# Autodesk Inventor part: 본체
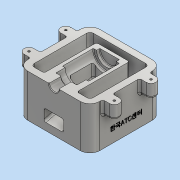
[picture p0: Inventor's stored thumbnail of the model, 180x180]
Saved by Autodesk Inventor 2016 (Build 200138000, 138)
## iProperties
Created: 2018-01
Part Number: 본체
Material: 알루미늄 6061
Document SubType Name: Modeling
Designer: Administrator
Density: 2.7 g/cm^3
Appearance: 알루미늄 - 평지
Mass: 995.217 g
Surface Area: 834.406 cm^2
Volume: 368.599 cm^3
Author: Administrator
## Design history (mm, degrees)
sketch "스케치1"
  geometry: L1 (-55, 55)-(55, 55); L2 (55, 55)-(55, -55); L3 (55, -55)-(-55, -55); L4 (-55, -55)-(-55, 55); L5 (-55, 55)-(55, -55); L6 (55, 55)-(-55, -55); 1 further point
  constraints: 12 end point, 2 midpoint, 2 parallel, 1 horizontal, 1 perpendicular
  dimensions: "d0" = 110 distance of L1.start L1.end; "d1" = 110 distance of L1.end L2.end
extrude "돌출1" new body sketch "스케치1" distance "d2" = 65; taper "d3" = 0 deg
feature "쉘1" dims "d4" = 10
sketch "스케치2"
  geometry: L1 (-45, 0)-(-45, 65) reference; L2 (-45, 8.564)-(35, 30); L3 (35, 30)-(35, 65); L4 (-45, 65)-(45, 65) reference; L5 (35, 65)-(-45, 65); L6 (-45, 65)-(-45, 8.564); L7 (45, 0)-(-45, 0) reference; L8 (55, 0)-(55, 65) reference; 1 further point
  constraints: 8 end point, 1 collinear, 1 parallel, 1 perpendicular, 1 point on line
  dimensions: "d5" = 30 distance from line of L7 L2.end; "d6" = 105 deg angle of L2 L1; "d7" = 20 distance between parallel lines of L8 L3
extrude "돌출2" join sketch "스케치2" stored distance "d8" = 50; taper "d9" = 0 deg
sketch "스케치3"
  geometry: L1 (-55, -55)-(55, -55) reference; L2 (0, -55)-(0, 30); L3 (0, 30)-(-15, 30); L4 (-15, 30)-(-15, 25); L5 (-15, 25)-(-20, 25); L6 (-20, 25)-(-20, -22); L7 (-20, -22)-(-16, -22); L8 (-16, -22)-(-16, -36); L9 (-16, -36)-(-7.5, -36); L10 (-7.5, -36)-(-7.5, -55); L11 (0, -55)-(-7.5, -55); 1 further point
  constraints: 20 end point, 9 perpendicular, 1 midpoint, 1 point on line, 1 vertical
  dimensions: "d10" = 30 diameter of L3.end L2; "d11" = 15 diameter of L10 L2; "d12" = 19 distance of L9.end L10.end; "d13" = 14 distance of L7.end L8.end; "d14" = 47 distance of L5.end L6.end; "d15" = 5 distance of L3.end L4.end; "d16" = 40 diameter of L6 L2; "d17" = 32 diameter of L8 L2
revolve "회전1" sketch "스케치3" stored, may be unused: angle "d18" = 90 deg
sketch "스케치5"
  geometry: L1 (-55, 0)-(-55, 65) reference; L2 (-55, 11.061)-(20, 31.157); L3 (20, 31.157)-(20, 65); L4 (-55, 29.061)-(-17, 39.243); L5 (-17, 39.243)-(-17, 65); L6 (35, 30)-(-45, 8.564) reference; L7 (-45, 65)-(35, 65) reference; L8 (25, 65)-(25, 50) reference; 1 further point
  constraints: 8 end point, 4 point on line, 3 parallel, 1 vertical
  dimensions: "d19" = 5 distance between parallel lines of L6 L2; "d20" = 18 distance of L2.start L4.start; "d21" = 37 distance between parallel lines of L3 L5; "d25" = 5 distance from line of L8 L3.end
extrude "돌출3" cut sketch "스케치5" stored distance "d23" = 30; taper "d24" = 0 deg
sketch "스케치6"
  geometry: L1 (-55, 55)-(-55, -55) reference; L2 (-55, -55)-(-7.5, -55) reference; L3 (-55, -35.5)-(-65, -35.5); L4 (-65, -35.5)-(-65, -20.5); L5 (-65, -20.5)-(-55, -20.5); L6 (-55, -20.5)-(-55, -35.5); A1 r 7.5 centre (-65, -28) between (-65, -20.5) and (-65, -35.5); 1 further point
  constraints: 8 end point, 2 parallel, 2 point on circle, 1 centre point, 1 horizontal, 1 midpoint, 1 perpendicular, 1 point on line
  dimensions: "d26" = 27 distance from line of L2 A1.centre; "d27" = 10 distance of L5.end L4.end; "d28" = 7.5 radius of A1
extrude "돌출4" join sketch "스케치6" distance "d29" = 20; taper "d30" = 0 deg
hole "구멍1" diameter "d33" = 3.242; stored, may be unused: countersink angle "d37" = 90 deg, drill point angle "d39" = 118 deg; dims "d31" = 10, "d32" = 10, "d34" = 9, "d35" = 4, "d36" = 2, "d38" = 11
fillet "모깎기1" dims "d43" = 5
fillet "모깎기2" dims "d44" = 15
sketch "스케치7"
  geometry: L1 (65, 75.5)-(65, 60.5) reference; L2 (0, -34.5)-(65, -34.5) reference; 2 further points
  constraints: 1 other
  dimensions: "d45" = 20 distance from line of L1 point (45, 20.5); "d46" = 55 distance from line of L2 point (45, 20.5)
feature "엠보싱1" sketch "스케치7" dims "d0" = 110, "d1" = 110, "d47" = 0.5, "d48" = 0
fillet "모깎기4" dims "d53" = 3
fillet "모깎기5" dims "d54" = 3
fillet "모깎기6" dims "d55" = 3
fillet "모깎기11" dims "d60" = 3
fillet "모깎기12" dims "d61" = 3
fillet "모깎기16" dims "d65" = 1
chamfer "모따기2" distance "d66" = 1; stored, may be unused: second distance "d67" = 2, angle "d68" = 45 deg
fillet "모깎기17" dims "d69" = 3
fillet "모깎기18" dims "d70" = 3
node "솔리드1"
pattern_linear "직사각형 패턴1" dims "d42" = 56
mirror "대칭1"
